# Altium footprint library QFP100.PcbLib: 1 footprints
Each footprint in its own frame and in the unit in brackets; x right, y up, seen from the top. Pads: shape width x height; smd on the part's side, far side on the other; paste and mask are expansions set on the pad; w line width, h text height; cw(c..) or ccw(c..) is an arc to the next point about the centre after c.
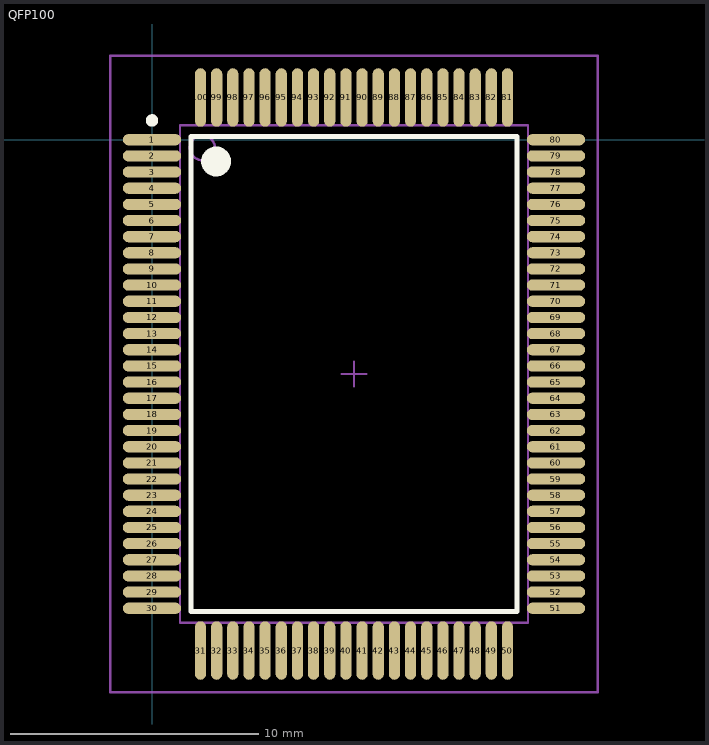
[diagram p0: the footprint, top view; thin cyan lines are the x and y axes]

## QFP100 [mm]
pads (100):
  oval 2.35x0.45 smd: 1(0,0) 2(0,-0.65) 3(0,-1.3) 4(0,-1.95) 5(0,-2.6) 6(0,-3.25) 7(0,-3.9) 8(0,-4.55) 9(0,-5.2) 10(0,-5.85) 11(0,-6.5) 12(0,-7.15) 13(0,-7.8) 14(0,-8.45) 15(0,-9.1) 16(0,-9.75) 17(0,-10.4) 18(0,-11.05) 19(0,-11.7) 20(0,-12.35) 21(0,-13) 22(0,-13.65) 23(0,-14.3) 24(0,-14.95) 25(0,-15.6) 26(0,-16.25) 27(0,-16.9) 28(0,-17.55) 29(0,-18.2) 30(0,-18.85) 51(16.25,-18.85) 52(16.25,-18.2) 53(16.25,-17.55) 54(16.25,-16.9) 55(16.25,-16.25) 56(16.25,-15.6) 57(16.25,-14.95) 58(16.25,-14.3) 59(16.25,-13.65) 60(16.25,-13) 61(16.25,-12.35) 62(16.25,-11.7) 63(16.25,-11.05) 64(16.25,-10.4) 65(16.25,-9.75) 66(16.25,-9.1) 67(16.25,-8.45) 68(16.25,-7.8) 69(16.25,-7.15) 70(16.25,-6.5) 71(16.25,-5.85) 72(16.25,-5.2) 73(16.25,-4.55) 74(16.25,-3.9) 75(16.25,-3.25) 76(16.25,-2.6) 77(16.25,-1.95) 78(16.25,-1.3) 79(16.25,-0.65) 80(16.25,0)
  oval 0.45x2.35 smd: 31(1.95,-20.55) 32(2.6,-20.55) 33(3.25,-20.55) 34(3.9,-20.55) 35(4.55,-20.55) 36(5.2,-20.55) 37(5.85,-20.55) 38(6.5,-20.55) 39(7.15,-20.55) 40(7.8,-20.55) 41(8.45,-20.55) 42(9.1,-20.55) 43(9.75,-20.55) 44(10.4,-20.55) 45(11.05,-20.55) 46(11.7,-20.55) 47(12.35,-20.55) 48(13,-20.55) 49(13.65,-20.55) 50(14.3,-20.55) 81(14.3,1.7) 82(13.65,1.7) 83(13,1.7) 84(12.35,1.7) 85(11.7,1.7) 86(11.05,1.7) 87(10.4,1.7) 88(9.75,1.7) 89(9.1,1.7) 90(8.45,1.7) 91(7.8,1.7) 92(7.15,1.7) 93(6.5,1.7) 94(5.85,1.7) 95(5.2,1.7) 96(4.55,1.7) 97(3.9,1.7) 98(3.25,1.7) 99(2.6,1.7) 100(1.95,1.7)
Top Overlay:
  circle w0.6: c2.575,-0.875 r0.3
  circle w0.25: c0,0.775 r0.125
  lines w0.2: 1.575,-18.975 14.675,-18.975 14.675,0.125 1.575,0.125 1.575,-18.975
Mechanical 13:
  circle w0.1: c2.025,-0.325 r0.5
  lines w0.1: 1.125,-19.425 15.125,-19.425 15.125,0.575 1.125,0.575 1.125,-19.425
Mechanical 15:
  lines w0.1: 7.625,-9.425 8.625,-9.425 ; 8.125,-9.925 8.125,-8.925 ; -1.675,-22.225 17.925,-22.225 17.925,3.375 -1.675,3.375 -1.675,-22.225
3D body: height 3.4, standoff 0, extent 1.125,-19.425 15.125,0.575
